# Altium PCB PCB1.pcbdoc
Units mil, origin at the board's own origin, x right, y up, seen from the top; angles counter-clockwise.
Board outline 1890 x 2457.31 mil, 2 copper layers (Top Layer, Bottom Layer); 30 components, 39 nets, 170 pads, 42 vias.
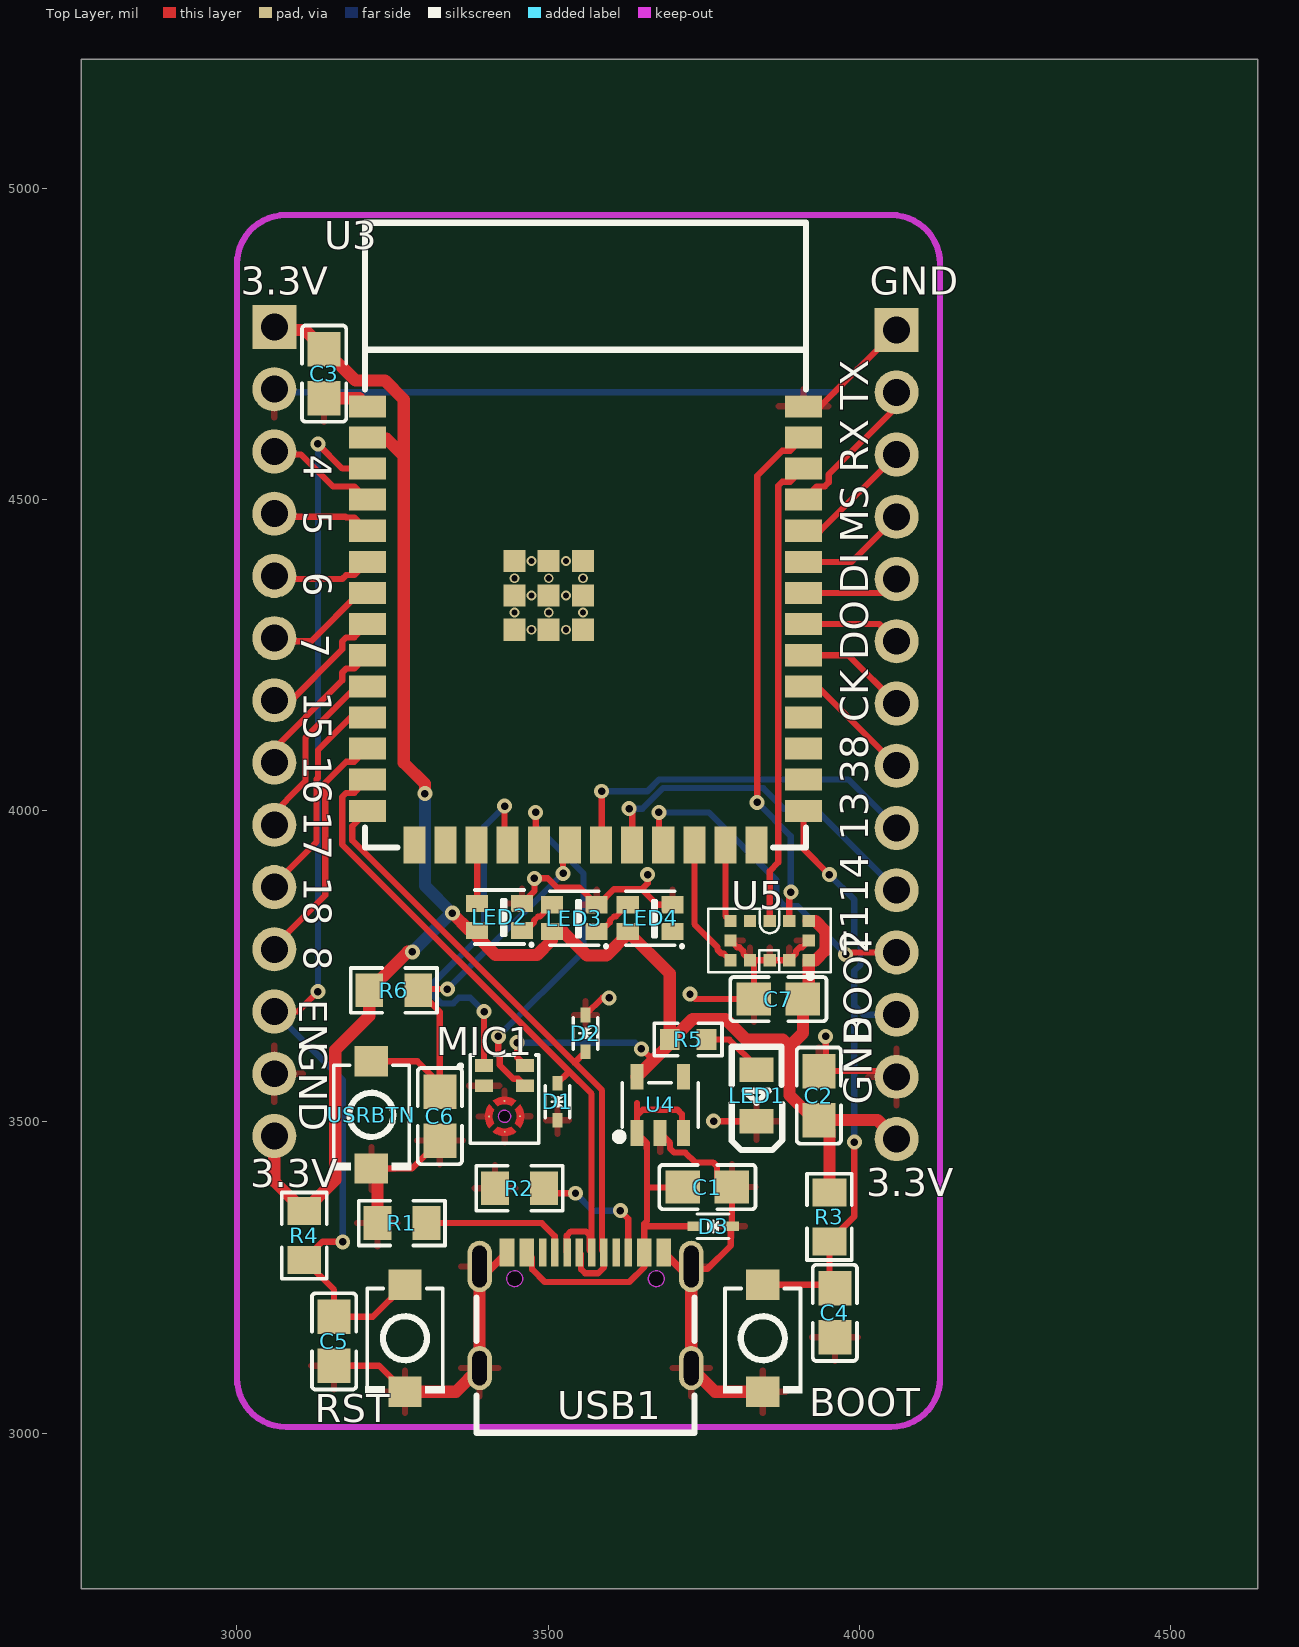
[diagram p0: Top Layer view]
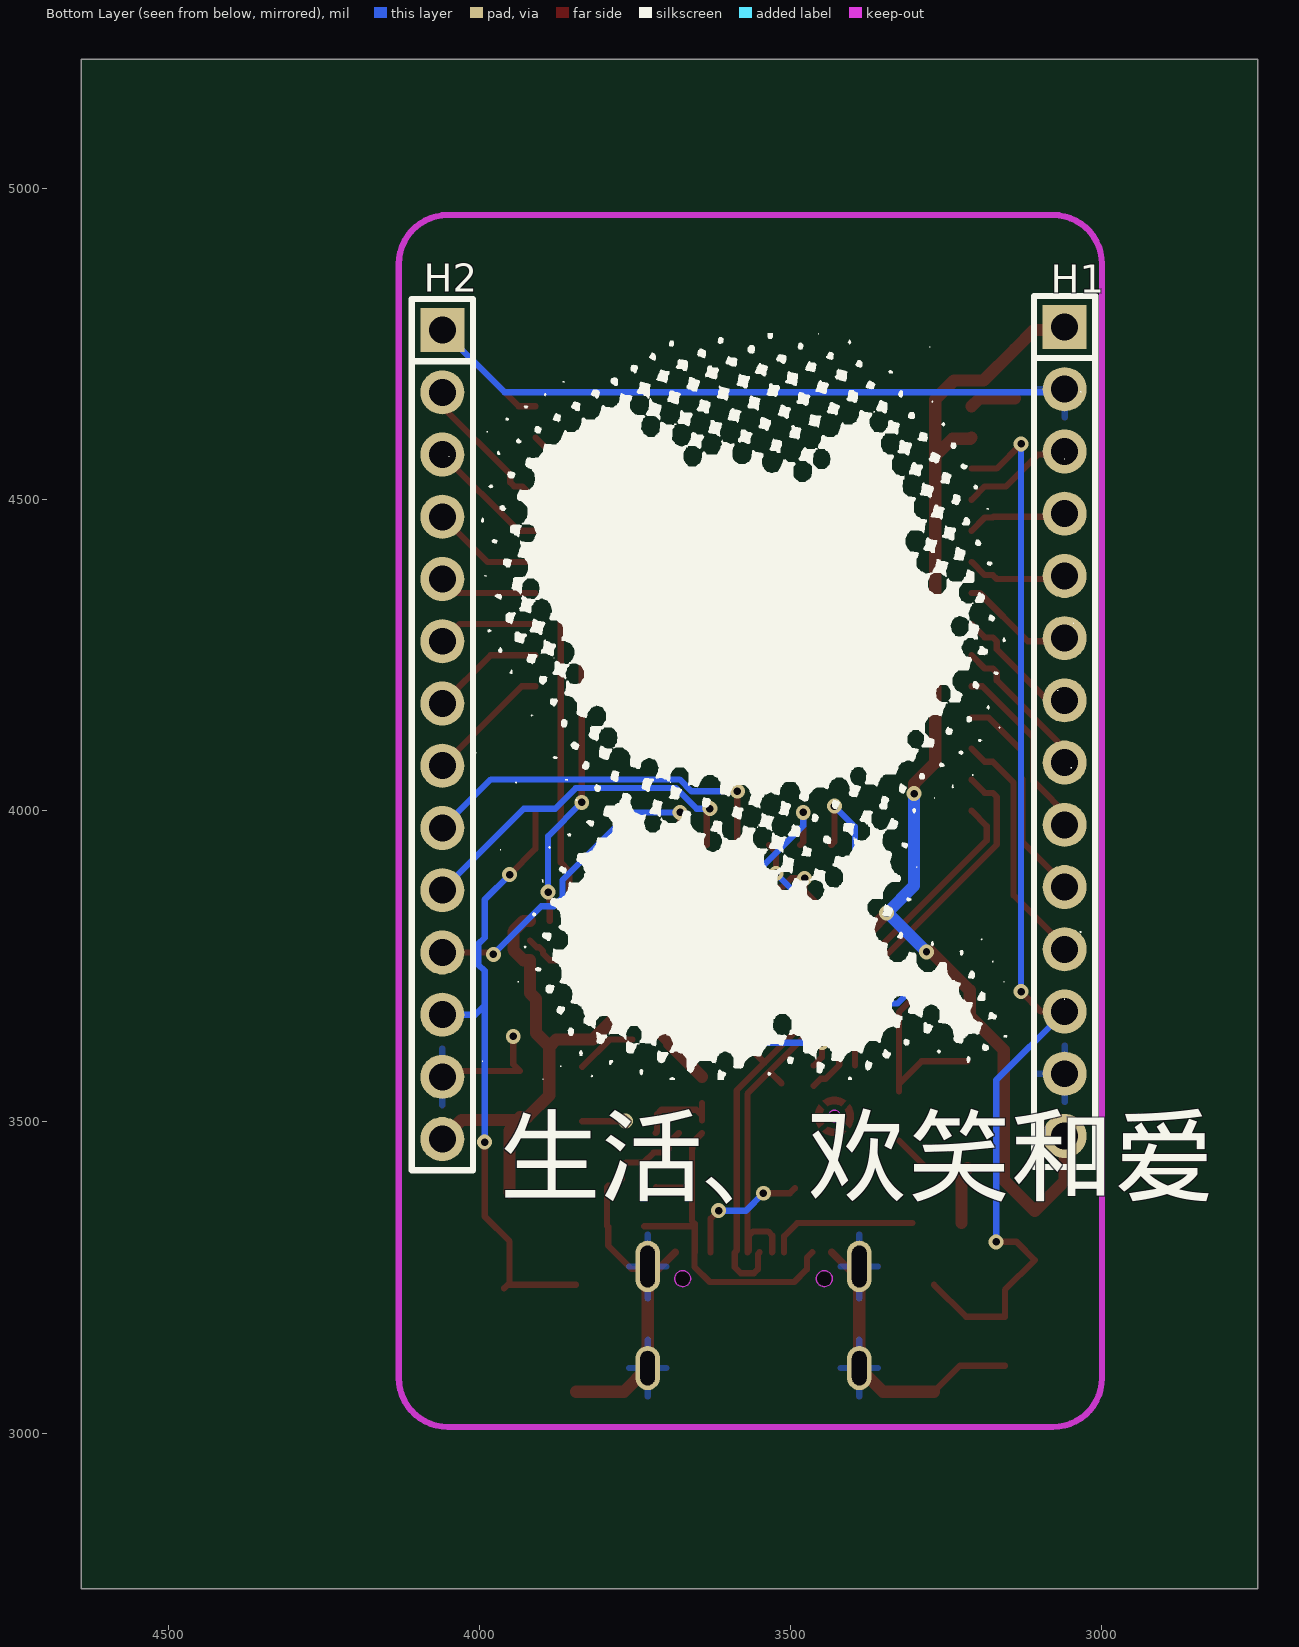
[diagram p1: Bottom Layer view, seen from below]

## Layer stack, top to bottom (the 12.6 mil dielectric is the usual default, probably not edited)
Top Layer: signal copper (thickness not stored)
Dielectric: dielectric 12.6, FR-4, Dk 4.8
Bottom Layer: signal copper (thickness not stored)

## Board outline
4640,2750 2750,2750 2750,5207.31 4640,5207.31

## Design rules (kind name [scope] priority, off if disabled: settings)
BoardOutlineClearance copperThickness1oz [All] p0: genericclearance=10 ignorepadtopadclearanceinfootprint=FALSE except(0: Arc-SplitContinuation Track-SplitContinuation SMDPad-SplitContinuation THPad-SplitContinuation Via-SplitContinuation Fill-SplitContinuation Poly-SplitContinuation Region-SplitContinuation Text-SplitContinuation; 6: Track-CutoutEdge SMDPad-CutoutEdge THPad-CutoutEdge Via-CutoutEdge Region-CutoutEdge; 11.8: Track-OutlineEdge SMDPad-OutlineEdge THPad-OutlineEdge Via-OutlineEdge Fill-OutlineEdge Region-OutlineEdge Poly-OutlineEdge Text-OutlineEdge Fill-CutoutEdge)
BoardOutlineClearance copperThickness2oz [All] p0: genericclearance=10 ignorepadtopadclearanceinfootprint=FALSE except(0: Arc-SplitContinuation Track-SplitContinuation SMDPad-SplitContinuation THPad-SplitContinuation Via-SplitContinuation Fill-SplitContinuation Poly-SplitContinuation Region-SplitContinuation Text-SplitContinuation; 6: Track-CutoutEdge SMDPad-CutoutEdge THPad-CutoutEdge Via-CutoutEdge Region-CutoutEdge; 11.8: Track-OutlineEdge SMDPad-OutlineEdge THPad-OutlineEdge Via-OutlineEdge Fill-OutlineEdge Region-OutlineEdge Poly-OutlineEdge Text-OutlineEdge Fill-CutoutEdge)
Clearance copperThickness1oz [(InNet('GND') OR InNet('$1N1348') OR InNet('+3.3V') OR InNet('BOOT') OR InNet('EN') OR InNet('USRBTN') OR InNet('D-') OR InNet('D+') OR InNet('GPIO11') OR InNet('GPIO10') OR InNet('GPIO8') OR InNet('GPIO18') OR InNet('GPIO17') OR InNet('GPIO16') OR InNet('GPIO15') OR InNet('GPIO7') OR InNet('GPIO6') OR InNet('GPIO5') OR InNet('GPIO4') OR InNet('GPIO21') OR InNet('GPIO14') OR InNet('GPIO13') OR InNet('MTCK') OR InNet('MTDO') OR InNet('MTDI') OR InNet('MTMS') OR InNet('RXD0') OR InNet('TXD0') OR InNet('$1N3564') OR InNet('NEO') OR InNet('$1N1566') OR InNet('$1N1581') OR InNet('TOFXSHUT') OR InNet('TOFGPIO1') OR InNet('TOFSDA') OR InNet('TOFSCL') OR InNet('GPIO38') OR InNet('$1N9702') OR InNet('$1N9708'))] p1: gap=7 ignorepadtopadclearanceinfootprint=FALSE except(4: Track-Track; 6: Track-SMDPad SMDPad-SMDPad Track-THPad SMDPad-THPad THPad-THPad Track-Via SMDPad-Via THPad-Via Via-Via SMDPad-Fill THPad-Fill Via-Fill Fill-Fill Track-Region SMDPad-Region THPad-Region Via-Region Region-Region Track-Poly SMDPad-Poly THPad-Poly Via-Poly Fill-Poly Region-Poly Poly-Poly Track-Text SMDPad-Text THPad-Text Via-Text Fill-Text Region-Text Poly-Text Text-Text; 6.9: Track-Hole SMDPad-Hole THPad-Hole Via-Hole Fill-Hole Region-Hole Poly-Hole Text-Hole Sheet-Hole; 11.8: Track-Fill Fill-Region Track-Sheet SMDPad-Sheet THPad-Sheet Via-Sheet Fill-Sheet Region-Sheet Poly-Sheet Text-Sheet)
Clearance copperThickness2oz [All] p1: gap=7 ignorepadtopadclearanceinfootprint=FALSE except(6: Track-SMDPad SMDPad-SMDPad Track-THPad SMDPad-THPad THPad-THPad Track-Via SMDPad-Via THPad-Via Via-Via SMDPad-Fill THPad-Fill Via-Fill Fill-Fill Track-Region SMDPad-Region THPad-Region Via-Region Region-Region Track-Poly SMDPad-Poly THPad-Poly Via-Poly Fill-Poly Region-Poly Poly-Poly Track-Text SMDPad-Text THPad-Text Via-Text Fill-Text Region-Text Poly-Text Text-Text; 6.9: Track-Hole SMDPad-Hole THPad-Hole Via-Hole Fill-Hole Region-Hole Poly-Hole Text-Hole Sheet-Hole; 8: Track-Track; 11.8: Track-Fill Fill-Region Track-Sheet SMDPad-Sheet THPad-Sheet Via-Sheet Fill-Sheet Region-Sheet Poly-Sheet Text-Sheet)
DiffPairsRouting differentialPair [All] p1: maxuncoupledlength=10 minlimit=6 maxlimit=6 mostfreqgap=6 toplayer_minwidth=5 toplayer_prefwidth=10 toplayer_maxwidth=100 bottomlayer_minwidth=5 bottomlayer_prefwidth=10 bottomlayer_maxwidth=100
PasteMaskExpansion pasteMaskExpansion [All] p1: expansion=0
PlaneConnect innerPlane [All] p1: planeconnectstyle=Relief reliefexpansion=20 reliefentries=4 reliefconductorwidth=10 reliefairgap=10
PolygonConnect copperRegion [All] p1: connectstyle=Relief reliefentries=4 reliefconductorwidth=10 polygonreliefangle="90 Angle" airgapwidth=10
RoutingVias viaSize [All] p1: viastyle="Through Hole" holewidth=12.0078 minholewidth=11.811 maxholewidth=248.0314 width=24.0158 minwidth=19.685 maxwidth=393.7008
SolderMaskExpansion solderMaskExpansion [All] p1: useseparateexpansions=TRUE expansion=2 expansionbottom=2
Width copperThickness1oz [All] p1: maxlimit=100 minlimit=5 preferedwidth=10
Width copperThickness2oz [All] p1: maxlimit=100 minlimit=8 preferedwidth=10

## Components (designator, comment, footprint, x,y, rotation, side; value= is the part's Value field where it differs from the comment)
BOOT "TS-1088-AR02016" SW-SMD_L3.9-W3.0-P4.45 3845,3152.32 r270 top
C1 "C0805B104K500NT" C0805 3756,3395.32 r0 top
C2 "C0805B104K500NT" C0805 3935,3542.32 r90 top
C3 "C0805B104K500NT" C0805 3140,4702.31 r270 top
C4 "C0805B104K500NT" C0805 3960.8,3193.14 r90 top
C5 "C0805B104K500NT" C0805 3156,3147.32 r90 top
C6 "C0805B104K500NT" C0805 3326,3509.32 r90 top
C7 "C0805B104K500NT" C0805 3870,3697.32 r180 top
D1 "LESD5D5.0CT1G" SOD-523_L1.2-W0.8-LS1.6-BI 3515,3532.32 r90 top
D2 "LESD5D5.0CT1G" SOD-523_L1.2-W0.8-LS1.6-BI 3560,3642.32 r270 top
D3 "LESD5D5.0CT1G" SOD-523_L1.2-W0.8-LS1.6-BI 3765,3332.32 r0 top
H1 "KH-2.54PH180-1X14P-L11.5" HDR-TH_14P-P2.54-V-M 3060,4127.31 r270 bottom
H2 "KH-2.54PH180-1X14P-L11.5" HDR-TH_14P-P2.54-V-M 4060,4122.31 r270 bottom
LED1 "NCD0805R1_C84256" LED0805-R-RD 3835,3542.32 r90 top
LED2 "WS2812B-2020" LED-SMD_4P-L2.0-W2.0-TL_WS2812B-2020 3422,3829.32 r180 top
LED3 "WS2812B-2020" LED-SMD_4P-L2.0-W2.0-TL_WS2812B-2020 3542,3827.32 r180 top
LED4 "WS2812B-2020" LED-SMD_4P-L2.0-W2.0-TL_WS2812B-2020 3664,3827.32 r180 top
MIC1 "MMICT390200012" MIC-SMD_5P-L3.5-W2.7-TL_MMICT390200012 3430,3537.32 r0 top
R1 "RMC08055.1K1%N" R0805 3265,3337.32 r180 top
R2 "RMC08055.1K1%N" R0805 3454,3393.32 r180 top
R3 "PTFR0805B10K0N9" R0805 3952,3347.32 r270 top
R4 "PTFR0805B10K0N9" R0805 3108,3317.32 r270 top
R5 "0603WAF1002T5E" R0603 3725,3632.32 r180 top
R6 "PTFR0805B10K0N9" R0805 3252,3711.32 r0 top
RST "TS-1088-AR02016" SW-SMD_L3.9-W3.0-P4.45 3270,3152.32 r270 top
U3 "ESP32-S3-WROOM-1-N8" WIFIM-SMD_ESP32-S3-WROOM-1-N8 3560,4297.31 r0 top
U4 "RT9080-33GJ5" TSOT-23-5_L2.9-W1.6-P0.95-LS2.8-BL 3680,3527.32 r0 top
U5 "VL53L4CXV0DH/1" OPTO-SMD_VL53L1CXV0FY-1 3856,3791.32 r0 top
USB1 "TYPE-C16PIN" USB-C-SMD_TYPE-C16PIN 3560,3197.32 r0 top
USRBTN "TS-1088-AR02016" SW-SMD_L3.9-W3.0-P4.45 3216,3511.32 r270 top

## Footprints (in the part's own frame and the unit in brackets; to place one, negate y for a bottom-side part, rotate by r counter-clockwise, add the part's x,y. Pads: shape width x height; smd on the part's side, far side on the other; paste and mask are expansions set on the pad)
C0805 [mm]
  rect 1.41x1.35 smd: 1(-1,0) 2(1,0)
  silkscreen extent -1.96,-0.9 1.96,0.9
HDR-TH_14P-P2.54-V-M [mm]
  rect 1.8x1.8 hole 1.1: 1(-16.51,0)
  round 1.8 hole 1.1: 2(-13.97,0) 3(-11.43,0) 4(-8.89,0) 5(-6.35,0) 6(-3.81,0) 7(-1.27,0) 8(1.27,0) 9(3.81,0) 10(6.35,0) 11(8.89,0) 12(11.43,0) 13(13.97,0) 14(16.51,0)
  silkscreen extent -17.78,-1.25 17.78,1.25
LED0805-R-RD [mm]
  rect 1x1.4 smd: 1(1.05,0) 2(-1.05,0)
  silkscreen extent -2.22,-1.04 1.99,1.01
LED-SMD_4P-L2.0-W2.0-TL_WS2812B-2020 [mm]
  rect 0.9x0.7 smd: 1(-0.915,0.55) 2(-0.915,-0.55) 3(0.915,-0.55) 4(0.915,0.55)
  silkscreen extent -1.3,-1.1 1,1.15
MIC-SMD_5P-L3.5-W2.7-TL_MMICT390200012 [mm]
  rect 0.725x0.522 smd: 1(-0.838,1.352) 2(-0.838,0.53) 4(0.838,0.53) 5(0.838,1.352)
  round 0.076 smd: 3(-0.629,-0.727) 3(-0.005,-0.093) 3(0.005,-1.352) 3(0.629,-0.717)
  Top Layer region: 0.487,-1.357 0.272,-1.142 0.272,-1.142 0.245,-1.158 0.217,-1.173 0.187,-1.186 0.157,-1.197 0.127,-1.206 0.095,-1.213 0.064,-1.218 0.032,-1.221 0,-1.222 -0.032,-1.221 -0.064,-1.218 -0.095,-1.213 -0.127,-1.206 -0.157,-1.197 -0.187,-1.186 -0.217,-1.173 -0.245,-1.158 -0.272,-1.142 -0.487,-1.357 -0.487,-1.357 -0.453,-1.381 -0.418,-1.404 -0.382,-1.425 -0.345,-1.444 -0.306,-1.461 -0.267,-1.476 -0.227,-1.489 -0.187,-1.5 -0.146,-1.509 -0.105,-1.515 -0.063,-1.52 -0.021,-1.522 0.021,-1.522 0.063,-1.52 0.104,-1.515 0.146,-1.509 0.187,-1.5 0.227,-1.489 0.267,-1.476 0.306,-1.461 0.345,-1.444 0.382,-1.425 0.418,-1.404 0.453,-1.381 0.487,-1.357
  Top Layer region: 0.634,-0.235 0.419,-0.45 0.419,-0.45 0.436,-0.477 0.451,-0.505 0.464,-0.535 0.475,-0.565 0.484,-0.595 0.491,-0.627 0.496,-0.658 0.499,-0.69 0.5,-0.722 0.499,-0.754 0.496,-0.786 0.491,-0.817 0.484,-0.849 0.475,-0.879 0.464,-0.909 0.451,-0.939 0.436,-0.967 0.419,-0.994 0.634,-1.209 0.634,-1.209 0.659,-1.175 0.682,-1.14 0.703,-1.104 0.722,-1.067 0.739,-1.028 0.754,-0.989 0.767,-0.949 0.778,-0.909 0.787,-0.868 0.793,-0.827 0.797,-0.785 0.8,-0.743 0.8,-0.701 0.797,-0.659 0.793,-0.618 0.787,-0.576 0.778,-0.535 0.767,-0.495 0.754,-0.455 0.739,-0.416 0.722,-0.377 0.703,-0.34 0.682,-0.304 0.659,-0.269 0.634,-0.235
  Top Layer region: -0.487,-0.088 -0.272,-0.303 -0.272,-0.303 -0.245,-0.286 -0.217,-0.272 -0.187,-0.259 -0.157,-0.248 -0.127,-0.239 -0.095,-0.232 -0.064,-0.226 -0.032,-0.223 0,-0.222 0.032,-0.223 0.064,-0.226 0.095,-0.232 0.127,-0.239 0.157,-0.248 0.187,-0.259 0.217,-0.272 0.245,-0.286 0.272,-0.303 0.487,-0.088 0.487,-0.088 0.453,-0.063 0.418,-0.04 0.382,-0.019 0.345,0 0.306,0.017 0.267,0.032 0.227,0.045 0.187,0.055 0.146,0.064 0.104,0.071 0.063,0.075 0.021,0.077 -0.021,0.077 -0.063,0.075 -0.104,0.071 -0.146,0.064 -0.187,0.056 -0.227,0.045 -0.267,0.032 -0.306,0.017 -0.345,0 -0.382,-0.019 -0.418,-0.04 -0.453,-0.063 -0.487,-0.088
  Top Layer region: -0.634,-1.21 -0.419,-0.995 -0.419,-0.995 -0.436,-0.967 -0.451,-0.939 -0.464,-0.91 -0.475,-0.88 -0.484,-0.849 -0.491,-0.818 -0.496,-0.786 -0.499,-0.754 -0.5,-0.722 -0.499,-0.69 -0.496,-0.658 -0.491,-0.627 -0.484,-0.596 -0.475,-0.565 -0.464,-0.535 -0.451,-0.506 -0.436,-0.477 -0.419,-0.45 -0.634,-0.235 -0.634,-0.235 -0.659,-0.269 -0.682,-0.304 -0.703,-0.34 -0.722,-0.378 -0.739,-0.416 -0.754,-0.455 -0.767,-0.495 -0.778,-0.535 -0.787,-0.576 -0.793,-0.618 -0.797,-0.659 -0.8,-0.701 -0.8,-0.743 -0.797,-0.785 -0.793,-0.827 -0.787,-0.868 -0.778,-0.909 -0.767,-0.95 -0.754,-0.989 -0.739,-1.029 -0.722,-1.067 -0.703,-1.104 -0.682,-1.14 -0.659,-1.176 -0.634,-1.209
  Board Outline Layer circle w0.005: c0,-0.722 r0.25
  Board Outline Layer region: 0.25,-0.722 0.225,-0.831 0.156,-0.918 0.056,-0.966 -0.056,-0.966 -0.156,-0.918 -0.225,-0.831 -0.25,-0.722 -0.25,-0.722 -0.225,-0.614 -0.156,-0.527 -0.056,-0.479 0.056,-0.479 0.156,-0.527 0.225,-0.614 0.25,-0.722
  Multi-Layer board cut-out: 0.25,-0.722 0.225,-0.831 0.156,-0.918 0.056,-0.966 -0.056,-0.966 -0.156,-0.918 -0.225,-0.831 -0.25,-0.722 -0.25,-0.722 -0.225,-0.614 -0.156,-0.527 -0.056,-0.479 0.056,-0.479 0.156,-0.527 0.225,-0.614 0.25,-0.722
  silkscreen extent -1.88,-1.82 1.4,1.78
OPTO-SMD_VL53L1CXV0FY-1 [mm]
  rect 0.5x0.5 smd: 1(1.6,-0.8) 2(0.8,-0.8) 3(0,-0.8) 4(-0.8,-0.8) 5(-1.6,-0.8) 6(-1.6,0) 7(-1.6,0.8) 8(-0.8,0.8) 9(0,0.8) 10(0.8,0.8) 11(1.6,0.8) 12(1.6,0)
  silkscreen extent -2.5,-1.52 2.5,1.3
R0603 [mil]
  rect 31.75x34.02 smd: 1(-29.66,0) 2(29.66,0)
  silkscreen extent -55,-26 55,26
R0805 [mm]
  rect 1.133x1.377 smd: 1(-1,0) 2(1,0)
  silkscreen extent -1.76,-0.92 1.76,0.92
SOD-523_L1.2-W0.8-LS1.6-BI [mm]
  rect 0.6x0.4 smd: 1(-0.75,0) 2(0.75,0)
  silkscreen extent -0.65,-0.5 0.65,0.5
SW-SMD_L3.9-W3.0-P4.45 [mm]
  rect 1.23x1.36 smd: 1(-2.185,0) 2(2.185,0)
  silkscreen extent -2.03,-1.62 2.25,1.62
TSOT-23-5_L2.9-W1.6-P0.95-LS2.8-BL [mm]
  rect 0.532x1.045 smd: 1(-0.95,-1.148) 2(0,-1.148) 3(0.95,-1.148) 4(0.95,1.148) 5(-0.95,1.148)
  silkscreen extent -1.82,-1.45 1.55,0.9
USB-C-SMD_TYPE-C16PIN [mm]
  oval 1x2.1 hole 0.6 slot 1.7 at 90 deg: 1(-4.32,1.787) 2(4.32,1.787)
  oval 1x1.8 hole 0.6 slot 1.4 at 90 deg: 3(-4.32,-2.362) 4(4.32,-2.362)
  rect 0.6x1.15 smd: A1B12(-3.2,2.362) A4B9(-2.4,2.362) B1A12(3.2,2.362) B4A9(2.4,2.362)
  rect 0.3x1.15 smd: A5(-1.25,2.362) A6(-0.25,2.362) A7(0.25,2.362) A8(1.25,2.362) B5(1.75,2.362) B6(0.75,2.362) B7(-0.75,2.362) B8(-1.75,2.362)
  Board Outline Layer circle w0.005: c2.89,1.288 r0.325
  Board Outline Layer circle w0.005: c-2.89,1.288 r0.325
  Board Outline Layer region: 3.215,1.288 3.183,1.147 3.093,1.034 2.962,0.971 2.818,0.971 2.687,1.034 2.597,1.147 2.565,1.288 2.565,1.288 2.597,1.429 2.687,1.542 2.818,1.605 2.962,1.605 3.093,1.542 3.183,1.429 3.215,1.288
  Board Outline Layer region: -2.565,1.288 -2.597,1.147 -2.687,1.034 -2.818,0.971 -2.962,0.971 -3.093,1.034 -3.183,1.147 -3.215,1.288 -3.215,1.288 -3.183,1.429 -3.093,1.542 -2.962,1.605 -2.818,1.605 -2.687,1.542 -2.597,1.429 -2.565,1.288
  Multi-Layer board cut-out: 3.215,1.288 3.183,1.147 3.093,1.034 2.962,0.971 2.818,0.971 2.687,1.034 2.597,1.147 2.565,1.288 2.565,1.288 2.597,1.429 2.687,1.542 2.818,1.605 2.962,1.605 3.093,1.542 3.183,1.429 3.215,1.288
  Multi-Layer board cut-out: -2.565,1.288 -2.597,1.147 -2.687,1.034 -2.818,0.971 -2.962,0.971 -3.093,1.034 -3.183,1.147 -3.215,1.288 -3.215,1.288 -3.183,1.429 -3.093,1.542 -2.962,1.605 -2.818,1.605 -2.687,1.542 -2.597,1.429 -2.565,1.288
  silkscreen extent -4.45,-5 4.45,0.52
WIFIM-SMD_ESP32-S3-WROOM-1-N8 [mm]
  rect 1.5x0.9 smd: 1(-8.9,8.955) 2(-8.9,7.685) 3(-8.9,6.415) 4(-8.9,5.145) 5(-8.9,3.875) 6(-8.9,2.605) 7(-8.9,1.335) 8(-8.9,0.065) 9(-8.9,-1.205) 10(-8.9,-2.475) 11(-8.9,-3.745) 12(-8.9,-5.015) 13(-8.9,-6.285) 14(-8.9,-7.555) 27(8.9,-7.555) 28(8.9,-6.285) 29(8.9,-5.015) 30(8.9,-3.745) 31(8.9,-2.475) 32(8.9,-1.205) 33(8.9,0.065) 34(8.9,1.335) 35(8.9,2.605) 36(8.9,3.875) 37(8.9,5.145) 38(8.9,6.415) 39(8.9,7.685) 40(8.9,8.955)
  rect 0.9x1.5 smd: 15(-6.985,-8.955) 16(-5.715,-8.955) 17(-4.445,-8.955) 18(-3.175,-8.955) 19(-1.905,-8.955) 20(-0.635,-8.955) 21(0.635,-8.955) 22(1.905,-8.955) 23(3.175,-8.955) 24(4.445,-8.955) 25(5.715,-8.955) 26(6.985,-8.955)
  rect 0.9x0.9 smd: 41(-2.9,-0.165) 41(-2.9,1.235) 41(-2.9,2.635) 41(-1.499,-0.165) 41(-1.499,1.235) 41(-1.499,2.635) 41(-0.099,-0.165) 41(-0.099,1.235) 41(-0.099,2.635)
  silkscreen extent -9,-9.05 9,16.45

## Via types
v1: diameter 24.02, hole 12.01, Top Layer to Bottom Layer, 30 vias
v2: diameter 15.75, hole 9.84, Top Layer to Bottom Layer, 12 vias

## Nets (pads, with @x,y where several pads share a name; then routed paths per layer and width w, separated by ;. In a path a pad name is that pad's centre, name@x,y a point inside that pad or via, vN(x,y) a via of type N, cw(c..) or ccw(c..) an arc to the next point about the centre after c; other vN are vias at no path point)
$1N1348: C1.1 D3.1 U4.1 U4.3 USB1.A4B9 USB1.B4A9 | length 732.8
  Top Layer w10: USB1.A4B9 3474.21,3281.62 3474.21,3263.14 3494.66,3242.69 3630.37,3242.69 3655,3267.32 3655,3289.82 USB1.B4A9 3654.49,3336.24 ; U4.1 3658.54,3466.19 3658.54,3457.01 3658.91,3456.65 3658.91,3394.39 ; U4.1@3642.6,3502.14 3642.6,3509.91 ; 3642.6,3529.91 3642.6,3509.91 ; C1.1 3715.71,3394.39 3658.91,3394.39 ; U4.3 3715,3484.53 3715,3512.32 3707.93,3519.39 3652.07,3519.39 3642.6,3509.91 ; D3.1 3658.42,3332.32 3654.49,3336.24 ; 3654.49,3336.24 3658.91,3340.66 3658.91,3394.39
$1N1566: R1.1 USB1.A5 | length 241.2
  Top Layer w10: R1.1 3490,3337.32 3510.79,3316.53 USB1.A5
$1N1581: R2.1 USB1.B5 | length 209.9
  Top Layer w10: R2.1 3501.37,3385.32 v1(3544,3385.32) ; v1(3616,3357.32) 3628.9,3344.41 USB1.B5
  Bottom Layer w10: v1(3544,3385.32) 3572,3357.32 v1(3616,3357.32)
$1N3564: LED1.1 R5.1 | length 98.4
  Top Layer w10: R5.1 3791.35,3632.32 LED1.1@3835,3588.66
$1N9702: LED2.1 LED3.3 | length 67
  Top Layer w9.45: LED2.1 3464.66,3807.66 3477.55,3820.54 3477.55,3823.88 3483.82,3830.15 3487.15,3830.15 LED3.3
$1N9708: LED3.1 LED4.3 | length 69.8
  Top Layer w9.45: LED3.1 3584.66,3805.66 3599.55,3820.54 3599.55,3823.88 3605.82,3830.15 3609.15,3830.15 LED4.3
+3.3V: C2.1 C3.1 C7.1 H1.1 H1.14 H2.14 LED2.4 LED3.4 LED4.4 MIC1.5 R3.1 R4.1 R5.2 R6.1 U3.2 U4.5 U5.1 U5.11 | length 3725.1
  Top Layer w10: v1(3450,3627.32) 3450,3603.52 MIC1.5 ; v1(3650,3617.32) 3667.82,3599.5 3667.82,3597.71
  Top Layer w19.68: H1.1@3050,4772.31 3109.37,4772.31 C3.1 3190.37,4691.31 3237.79,4691.31 3268.13,4660.97 3268.13,4570.13 ; H1.14 3060,3404.68 R4.1 3158,3406.68 3158,3615.32 3212.63,3669.95 R6.1 3274.63,3773.32 v1(3282,3773.32) ; U3.2 3211.61,4597.86 3240.39,4597.86 3268.13,4570.13 ; v1(3302,4027.32) 3302,4043.32 3268.13,4077.19 3268.13,4570.13 ; v1(3346,3835.32) 3373.66,3807.66 LED2.4 3385.97,3797.66 3415.58,3768.05 3482.3,3768.05 3505.97,3791.73 LED3.4 3524.15,3805.66 3562.49,3767.32 3593.56,3767.32 3627.97,3801.73 LED4.4 3695.34,3738.3 R5.2 ; U4.5 3667.82,3597.71 3695.34,3625.24 R5.2 ; U5.11 3929.57,3822.81 3944.66,3807.72 3944.66,3806.87 3945.82,3805.71 3945.82,3776.93 3944.66,3775.77 3944.66,3774.92 3929.56,3759.82 U5.1 3918.99,3706.93 C7.1 3909.37,3642.68 3888,3621.32 ; R3.1 3952,3485.95 C2.1 ; H2.14 4029.37,3502.95 C2.1 ; R5.2 3699.39,3632.32 3732.23,3665.15 3785.18,3665.15 3818.02,3632.32 3877,3632.32 3888,3621.32 ; 3888,3621.32 3888,3542.9 3923.58,3507.32 3935.22,3507.32 3935,3507.09 C2.1
  Bottom Layer w10: v1(3450,3627.32) 3640,3627.32 v1(3650,3617.32)
  Bottom Layer w19.68: v1(3282,3773.32) 3344,3835.32 v1(3346,3835.32) 3302,3879.32 v1(3302,4027.32)
BOOT: BOOT.1 C4.2 H2.12 R3.2 U3.27 | length 1013.8
  Top Layer w10: BOOT.1 C4.2@3954.97,3238.34 ; U3.27 3910.39,3938.93 v1(3952,3897.32) ; C4.2 C4.2@3954.97,3238.34 ; v1(3992,3467.32) 3992,3347.95 R3.2 3952,3241.3 C4.2@3954.97,3238.34
  Bottom Layer w10: v1(3952,3897.32) 3992,3857.32 3992,3795.83 4002,3785.83 4002,3752.8 3992,3742.8 3992,3687.32 ; v1(3992,3467.32) 3992,3687.32 ; H2.12 4007,3672.32 3992,3687.32
D+: D2.2 U3.14 USB1.A6 USB1.B6 | length 1008.7
  Top Layer w10: U3.14 3185.1,3975.35 3185.1,3952.21 3542.61,3594.71 ; USB1.A6 3552.95,3287.53 3552.95,3263.14 3559.38,3256.7 3580.3,3256.7 3590,3266.41 3590,3289.86 USB1.B6 3586.73,3293.13 3586.73,3550.59 3542.61,3594.71 ; D2.2 3542.61,3595.4 3542.61,3594.71
D-: D1.2 U3.13 USB1.A7 USB1.B7 | length 1075.7
  Top Layer w10: U3.13 3188.32,4028.56 3175.54,4028.56 3169.1,4022.13 3169.1,3945.58 3531.93,3582.75 ; D1.2 3531.93,3578.77 3531.93,3582.75 ; USB1.B7 3530,3290.8 3530,3317.32 3536.63,3323.95 3560.62,3323.95 3567.05,3317.51 3567.05,3293.12 USB1.A7 3569.84,3544.85 3531.93,3582.75
EN: C5.2 H1.12 R4.2 RST.1 U3.3 | length 1795.5
  Top Layer w10: H1.12 3098,3677.32 v1(3130,3709.32) ; v1(3130,4589.31) 3169.45,4549.86 U3.3 ; v1(3170,3307.32) 3137.37,3307.32 R4.2 3156,3229.95 C5.2 3218.35,3186.68 RST.1
  Bottom Layer w10: H1.12 3170,3567.32 v1(3170,3307.32) ; v1(3130,3709.32) v1(3130,4589.31)
GND: BOOT.2 C1.2 C2.2 C3.2 C4.1 C5.1 C6.1 C7.2 D1.1 D2.1 D3.2 H1.2 H1.13 H2.1 H2.13 LED1.2 LED2.2 LED3.2 LED4.2 MIC1.2 MIC1.3 R1.2 R2.2 RST.2 U3.1 U3.40 U4.2 U5.2 U5.3 U5.4 U5.6 U5.12 USB1.1 USB1.2 USB1.3 USB1.4 USB1.A1B12 USB1.B1A12 USRBTN.2 | length 3689
  Top Layer w10: C5.1 3228.35,3107.95 RST.2 ; USRBTN.2 3281.35,3425.3 C6.1 ; USB1.1@3380,3262.32 USB1.1@3389.92,3262.32 ; LED2.2 3478,3870.95 v1(3478,3891.32) 3499.48,3891.32 3514.48,3876.32 3550.67,3876.32 LED3.2 3580.94,3848.97 3605.71,3873.73 3650.24,3873.73 ; D2.1 3587.47,3699.32 v1(3598,3699.32) ; v1(3660,3897.32) 3660,3883.49 3650.24,3873.73 ; U4.2 3695.94,3466.19 3695.94,3457.01 3702.38,3450.58 3720.38,3450.58 3736.08,3434.87 3764.94,3434.87 3771.37,3428.44 3771.37,3408.76 3782.82,3397.32 3793.37,3397.32 C1.2 3795.37,3333.16 D3.2 3793.53,3331.32 3793.53,3301.13 3756.08,3263.68 3734.08,3263.68 USB1.2 ; LED4.2 3675.01,3848.97 3650.24,3873.73 ; v1(3728,3705.32) 3736,3697.32 C7.2 3830.63,3753.69 U5.4 U5.3 U5.2 3898.16,3770.49 3898.16,3774.21 3904.6,3780.65 3908.32,3780.65 U5.12 ; v1(3766,3501.32) 3766.35,3500.97 LED1.2 ; U5.6 3803.68,3780.65 3807.4,3780.65 3813.84,3774.21 3813.84,3770.49 U5.4 ; U3.40 3937.55,4649.86 H2.1 ; v1(3946,3637.32) 3946,3592.68 C2.2 4050.63,3581.68 H2.13
  Top Layer w11.81: USB1.1@3389.92,3262.32 3406,3262.32 USB1.A1B12 ; USB1.B1A12 3728.17,3248.13 USB1.2@3730.08,3248.13
  Top Layer w19.68: C3.2 3196.53,4662.94 U3.1 ; USRBTN.2 3225.63,3415.66 R1.2 ; RST.2 3351.91,3066.3 USB1.3 USB1.1@3389.92,3262.32 ; USB1.2@3730.08,3248.13 USB1.4 3768.09,3066.3 BOOT.2
  Bottom Layer w10: H1.2@3050,4672.31 3960,4672.31 H2.1
GPIO4: H1.3 U3.4 | length 189.6
  Top Layer w10: H1.3@3050,4572.31 3103,4572.31 3154.16,4521.16 3188.32,4521.16 U3.4
GPIO5: H1.4 U3.5 | length 168.9
  Top Layer w10: H1.4@3050,4472.31 3174.38,4472.31 3175.54,4471.16 3188.32,4471.16 U3.5
GPIO6: H1.5 U3.6 | length 171
  Top Layer w10: H1.5@3050,4372.31 3169.29,4372.31 3175.54,4378.56 3188.32,4378.56 U3.6
GPIO7: H1.6 U3.7 | length 191.7
  Top Layer w10: H1.6@3050,4272.31 3119.29,4272.31 3196.84,4349.86 U3.7
GPIO8: H1.11 U3.12 | length 401.1
  Top Layer w10: H1.11@3050,3772.32 3142,3864.32 3142,4045.02 3175.54,4078.56 3188.32,4078.56 U3.12
GPIO10: MIC1.1 U3.18 | length 603
  Top Layer w10: MIC1.1 v1(3397.01,3677.32) ; v1(3430,4007.32) 3430,3949.78 U3.18
  Bottom Layer w10: v1(3397.01,3677.32) 3375.03,3699.3 3356.5,3699.3 3347.52,3690.32 3328.48,3690.32 3315.01,3703.79 3315.01,3722.84 3397.01,3804.84 3397.01,3974.32 v1(3430,4007.32)
GPIO11: MIC1.4 U3.19 | length 604.7
  Top Layer w10: v1(3420,3637.32) 3420,3607.62 3422.27,3605.36 3422.27,3591.17 3444.17,3569.27 3451.89,3569.27 MIC1.4 ; v1(3480,3997.32) 3480,3949.78 U3.19
  Bottom Layer w10: v1(3420,3637.32) 3556.99,3774.31 3556.99,3898.84 3480,3975.83 v1(3480,3997.32)
GPIO13: H2.9 U3.21 | length 601.1
  Top Layer w10: U3.21 3586,3945.76 v1(3586,4031.32)
  Bottom Layer w10: v1(3586,4031.32) 3659.66,4031.32 3678.67,4050.32 3981.99,4050.32 H2.9
GPIO14: H2.10 U3.22 | length 572.2
  Top Layer w10: v1(3630,4003.32) 3635.01,3998.31 U3.22
  Bottom Layer w10: v1(3630,4003.32) 3651.48,4003.32 3684.48,4036.31 3845.52,4036.31 3878.52,4003.32 3929,4003.32 H2.10
GPIO15: H1.7 U3.8 | length 219.9
  Top Layer w10: H1.7@3050,4172.31 3082.07,4172.31 3169.1,4259.35 3169.1,4272.13 3175.54,4278.56 3188.32,4278.56 U3.8
GPIO16: H1.8 U3.9 | length 251.1
  Top Layer w10: H1.8@3050,4072.32 3050,4090.24 3169.1,4209.35 3169.1,4222.13 3175.54,4228.56 3188.32,4228.56 U3.9
GPIO17: H1.9 U3.10 | length 303.7
  Top Layer w10: H1.9@3050,3972.32 3050,3987.32 3110,4047.32 3110,4117.31 3192.55,4199.86 U3.10
GPIO18: H1.10 U3.11 | length 359.5
  Top Layer w10: H1.10@3050,3872.32 3127.98,3950.3 3127.98,4050.83 3130,4052.84 3130,4097.31 3182.55,4149.86 U3.11
GPIO21: H2.11 U3.23 | length 549.8
  Top Layer w10: v1(3678,3997.32) 3678,3951.78 U3.23 ; v1(3978,3769.32) 3981,3772.32 H2.11
  Bottom Layer w10: v1(3678,3997.32) 3758,3997.32 3867.01,3888.31 3867.01,3859.79 3880.48,3846.32 3900.99,3846.32 v1(3978,3769.32)
GPIO38: H2.8 U3.31 | length 202.4
  Top Layer w10: U3.31 3932.45,4199.86 H2.8
MTCK: H2.7 U3.32 | length 181.7
  Top Layer w10: U3.32 3982.45,4249.86 H2.7
MTDI: H2.5 U3.34 | length 158.9
  Top Layer w10: U3.34 4037.55,4349.86 H2.5
MTDO: H2.6 U3.33 | length 161
  Top Layer w10: U3.33 4032.45,4299.86 H2.6
MTMS: H2.4 U3.35 | length 179.6
  Top Layer w10: U3.35 3987.55,4399.86 H2.4
NEO: LED2.3 U3.17 | length 94.2
  Top Layer w10: U3.17 3385.97,3943.8 LED2.3
RXD0: H2.3 U3.36 | length 200.3
  Top Layer w10: U3.36 3937.55,4449.86 H2.3
TOFGPIO1: U3.25 U5.7 | length 125.3
  Top Layer w10: U3.25 3785.01,3830.82 U5.7
TOFSCL: U3.39 U5.10 | length 838.8
  Top Layer w10: v1(3836,4013.32) 3836,4538.25 3876.31,4578.56 3889.09,4578.56 U3.39 ; U5.10 3887.49,3866.8 v1(3890,3869.32)
  Bottom Layer w10: v1(3836,4013.32) 3890,3959.32 v1(3890,3869.32)
TOFSDA: U3.38 U5.9 | length 757.1
  Top Layer w10: U5.9 3856,3902.99 3869.87,3916.86 3869.87,4522.13 3876.31,4528.56 3889.09,4528.56 U3.38
TOFXSHUT: U3.24 U5.5 | length 211.2
  Top Layer w10: U3.24 3735.01,3817.82 3772.18,3780.65 3772.18,3776.93 3778.62,3770.49 3782.34,3770.49 U5.5
TXD0: H2.2 U3.37 | length 241.9
  Top Layer w10: U3.37 3931.68,4521.16 3944.46,4521.16 3950.9,4527.59 3950.9,4540.37 4060,4649.48 H2.2
USRBTN: C6.2 R6.2 U3.20 USRBTN.1 | length 662.4
  Top Layer w10: USRBTN.1 3289.98,3597.34 C6.2@3326,3561.32 ; C6.2 C6.2@3326,3561.32 ; v1(3338,3713.32) 3293.37,3713.32 R6.2 3326,3676.68 C6.2@3326,3561.32 ; v1(3524,3899.32) 3524,3933.76 U3.20
  Bottom Layer w10: v1(3338,3713.32) v1(3524,3899.32)
pads on no net: LED4.1 U3.15 U3.16 U3.26 U3.28 U3.29 U3.30 U3.41 U4.4 U5.8 USB1.A8 USB1.B8
copper on no net:
  other v2: 3473.39,4290.82 3528.51,4290.82 3445.84,4318.38 3500.95,4318.38 3556.07,4318.38 3473.39,4345.94 3528.51,4345.94 3445.84,4373.5 3500.95,4373.5 3556.07,4373.5 3473.39,4401.06 3528.51,4401.06

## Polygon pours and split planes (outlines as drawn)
GND on Bottom Layer (solid, remove dead copper, pour order 2): 3005,4722.31 4105,4722.31 4105,3022.32 3005,3022.32
GND on Top Layer (solid, remove dead copper, pour order 0): 3007,4722.31 4107,4722.31 4107,3022.32 3007,3022.32

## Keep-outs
Board Outline Layer:
  lines w10: 3000,3088.5 ccw(c3078.74,3088.5) 3078.74,3009.76 4051.18,3009.76 ccw(c4051.18,3088.5) 4129.92,3088.5 4129.92,4878.57 ccw(c4051.18,4878.57) 4051.18,4957.32 3078.74,4957.31 ccw(c3078.74,4878.57) 3000,4878.57 3000,3088.5

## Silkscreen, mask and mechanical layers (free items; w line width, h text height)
Top Silkscreen Layer:
  text "3.3V" at 3006,4829.31 h45
  text "GND" at 4017.2,4828.81 h45
  text "TX" at 4014.5,4644.52 h45 r90
  text "4" at 3107.5,4572.08 h45 r270
  text "RX" at 4014.5,4543.32 h45 r90
  text "5" at 3107.5,4481.33 h45 r270
  text "MS" at 4014.5,4430.37 h45 r90
  text "6" at 3107,4383.11 h45 r270
  text "DI" at 4014.5,4348.42 h45 r90
  text "7" at 3103,4284.41 h45 r270
  text "DO" at 4014.5,4241.52 h45 r90
  text "15" at 3107.5,4191.43 h45 r270
  text "CK" at 4014.5,4142.12 h45 r90
  text "16" at 3107.5,4089.01 h45 r270
  text "38" at 4014.5,4043.43 h45 r90
  text "17" at 3107.5,3999.46 h45 r270
  text "13" at 4014.5,3951.42 h45 r90
  text "18" at 3107.5,3893.66 h45 r270
  text "14" at 4014.5,3851.03 h45 r90
  text "8" at 3107,3782.41 h45 r270
  text "21" at 4014.5,3769.83 h45 r90
  text "EN" at 3100,3697.32 h45 r270
  text "GND" at 3100,3627.32 h45 r270
  text "BOOT" at 4020,3627.32 h45 r90
  text "GND" at 4020,3527.32 h45 r90
  text "3.3V" at 3021.2,3394.82 h45
  text "3.3V" at 4011.2,3380.34 h45
Bottom Silkscreen Layer:
  drawing of 215 lines, arcs and shapes, not listed
  text "生活、欢笑和爱" at 3970,3387.32 h120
